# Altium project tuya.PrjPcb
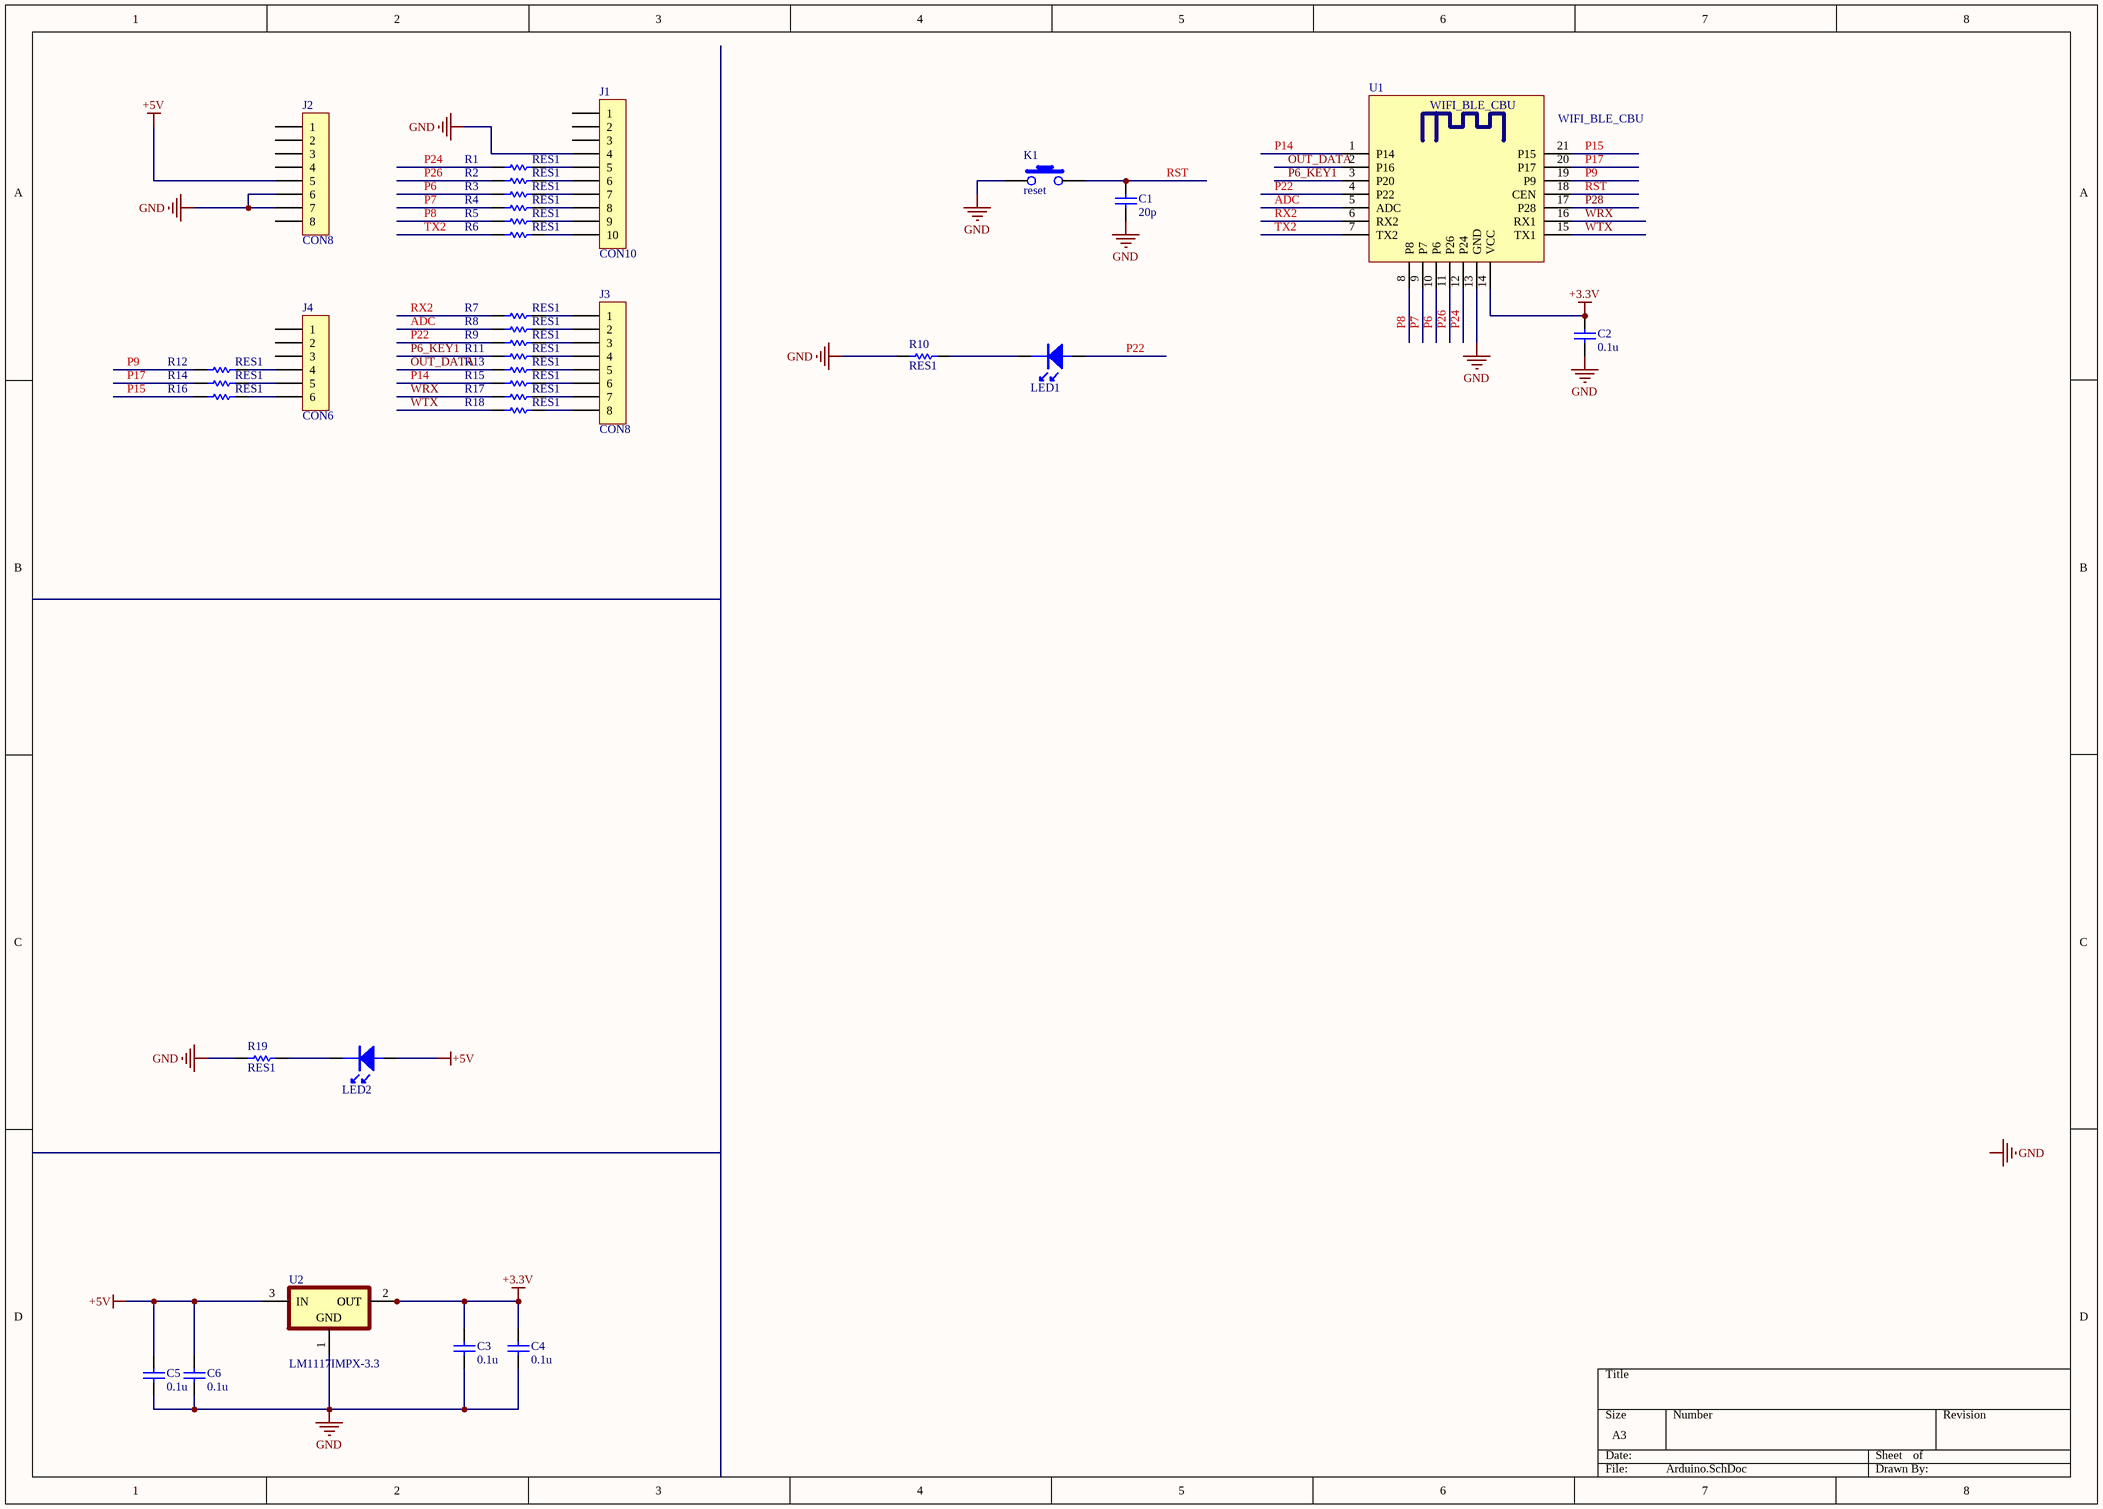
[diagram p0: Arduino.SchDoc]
1 sheet, 34 parts. Net scope: global (net labels, ports and power ports of the same name join across sheets).
Board file: Arduino.PcbDoc

## Sheet Arduino.SchDoc
size A3

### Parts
C1  20p  [C0603]
C2  0.1u  [C0603]
C3  0.1u  [C0603]
C4  0.1u  [C0603]
C5  0.1u  [C0603]
C6  0.1u  [C0603]
J1  CON10  [HDR1X10Z]
J2  CON8  [HDR1X8Z]
J3  CON8  [HDR1X8Z]
J4  CON6  [HDR1X6Z]
K1  reset  [KEY-MM-Half-SMT]
LED1  LED  [D0805]  (value not drawn)
LED2  LED  [D0805]  (value not drawn)
R1  RES1  [R0603]
R2  RES1  [R0603]
R3  RES1  [R0603]
R4  RES1  [R0603]
R5  RES1  [R0603]
R6  RES1  [R0603]
R7  RES1  [R0603]
R8  RES1  [R0603]
R9  RES1  [R0603]
R10  RES1  [R0603]
R11  RES1  [R0603]
R12  RES1  [R0603]
R13  RES1  [R0603]
R14  RES1  [R0603]
R15  RES1  [R0603]
R16  RES1  [R0603]
R17  RES1  [R0603]
R18  RES1  [R0603]
R19  RES1  [R0603]
U1  WIFI_BLE_CBU  [WIFI_BLE_CBU]
U2  LM1117IMPX-3.3  [SOT-223]

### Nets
+3.3V: C2.1 C3.1 C4.1 U1.14(VCC) U2.2(OUT) U2.4(OUT)
+5V: C5.1 C6.1 J2.5 LED2.2(A) U2.3(IN)
GND: C1.1 C2.2 C3.2 C4.2 C5.2 C6.2 J1.4 J2.6 J2.7 K1.1 R10.1 R19.1 U1.13(GND) U2.1(GND)
ADC: R8.1 U1.5(ADC)
OUT_DATA: R13.1 U1.2(P16)
P6: R3.1 U1.10(P6)
P6_KEY1: R11.1 U1.3(P20)
P7: R4.1 U1.9(P7)
P8: R5.1 U1.8(P8)
P9: R12.1 U1.19(P9)
P14: R15.1 U1.1(P14)
P15: R16.1 U1.21(P15)
P17: R14.1 U1.20(P17)
P22: LED1.2(A) R9.1 U1.4(P22)
P24: R1.1 U1.12(P24)
P26: R2.1 U1.11(P26)
P28: U1.17(P28)
RST: C1.2 K1.2 U1.18(CEN)
RX2: R7.1 U1.6(RX2)
TX2: R6.1 U1.7(TX2)
WRX: R17.1 U1.16(RX1)
WTX: R18.1 U1.15(TX1)
NetJ1_5: J1.5 R1.2
NetJ1_6: J1.6 R2.2
NetJ1_7: J1.7 R3.2
NetJ1_8: J1.8 R4.2
NetJ1_9: J1.9 R5.2
NetJ1_10: J1.10 R6.2
NetJ3_1: J3.1 R7.2
NetJ3_2: J3.2 R8.2
NetJ3_3: J3.3 R9.2
NetJ3_4: J3.4 R11.2
NetJ3_5: J3.5 R13.2
NetJ3_6: J3.6 R15.2
NetJ3_7: J3.7 R17.2
NetJ3_8: J3.8 R18.2
NetJ4_4: J4.4 R12.2
NetJ4_5: J4.5 R14.2
NetJ4_6: J4.6 R16.2
NetLED1_1: LED1.1(K) R10.2
NetLED2_1: LED2.1(K) R19.2

Not connected (* = marked no-connect by the designer): J1 1 2 3; J2 1 2 3 4 8; J4 1 2 3

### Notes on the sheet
- Labels drawn without touching a wire or pin: GND

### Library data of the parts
C1-C6 = Cap: Capacitor
J1 = CON10: Connector
J2 J3 = CON8: Connector
J4 = CON6: Connector
K1 = KEY
R1-R19 = RES1: Resistor
U1 = WIFI_BLE_CBU: Module
U2 = LM1117IMPX-3.3: 800mA Low-Dropout Linear Regulator; P/N: 120-0010-000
